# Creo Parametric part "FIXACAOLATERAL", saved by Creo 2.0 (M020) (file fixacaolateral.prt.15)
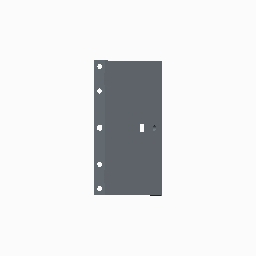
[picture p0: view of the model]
Units: millimeter Newton Second (mmNs); MM, TONNE, SECS

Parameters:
  PTC_COMMON_NAME = "fixacaolateral.prt"
  METRIC = "YES"

Other parameters: DRILL_POINT_ANGLE, DRILL_DEPTH, DRILL_DIAMETER, THREAD_DIAMETER, THREADS_PER_INCH, THREAD_DEPTH

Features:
  1. datum plane "RIGHT"
  2. datum plane "TOP"
  3. datum plane "FRONT"
  4. coordinate system
  5. protrusion "Section 1"
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
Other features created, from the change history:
  sketch "Sketch 1"
  extruded cut "Extrude 3"
  sketch "Sketch 2"
  extruded cut "Extrude 4"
